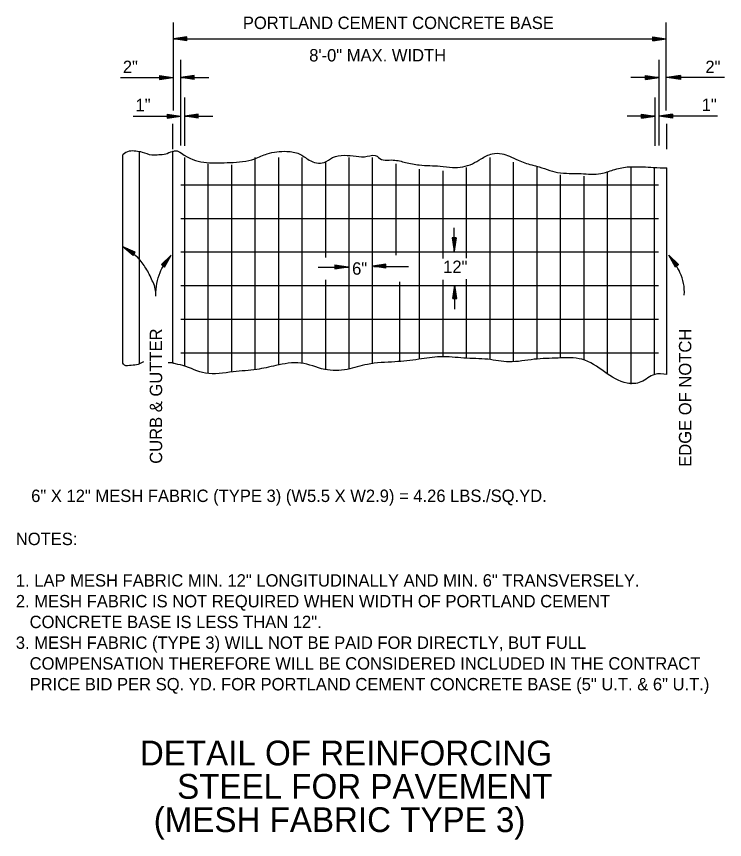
# Model space of a CAD drawing. Extents: x 635488 to 635865, y 290537 to 290973.
# Drawn here: x 635642.05 to 635676.35, y 290881.35 to 290921.21 of the extents above; entities that cross this region are included whole.
import ezdxf

# ---------------------------------------------------------------- set-up
doc = ezdxf.new("R2010")
doc.units = 0
doc.layers.add('E_Existing ROW', color=7, linetype='Continuous')

msp = doc.modelspace()

# ---------------------------------------------------------------- linework, layer by layer
at = {"layer": 'E_Existing ROW'}
for p, q in [((635649.657, 290916.655), (635649.657, 290920.918)), ((635673.528, 290916.655), (635673.528, 290920.918)), ((635650.307, 290920.228), (635649.657, 290920.13)), ((635649.657, 290920.13), (635673.528, 290920.13)), ((635650.307, 290920.033), (635649.657, 290920.13)), ((635650.307, 290920.211), (635649.765, 290920.13)), ((635650.307, 290920.049), (635649.765, 290920.13)), ((635650.307, 290920.195), (635649.877, 290920.13)), ((635650.307, 290920.066), (635649.877, 290920.13)), ((635650.307, 290920.178), (635649.985, 290920.13)), ((635650.307, 290920.082), (635649.985, 290920.13)), ((635650.307, 290920.162), (635650.096, 290920.13)), ((635650.307, 290920.099), (635650.096, 290920.13)), ((635650.307, 290920.145), (635650.204, 290920.13)), ((635650.307, 290920.115), (635650.204, 290920.13)), ((635650.307, 290920.033), (635650.307, 290920.228)), ((635672.879, 290920.228), (635673.529, 290920.13)), ((635672.879, 290920.033), (635672.879, 290920.228)), ((635672.879, 290920.211), (635673.42, 290920.13)), ((635672.879, 290920.195), (635673.309, 290920.13)), ((635672.879, 290920.178), (635673.201, 290920.13)), ((635672.879, 290920.162), (635673.09, 290920.13)), ((635672.879, 290920.145), (635672.981, 290920.13)), ((635672.879, 290920.033), (635673.529, 290920.13)), ((635672.879, 290920.099), (635673.09, 290920.13)), ((635672.879, 290920.066), (635673.309, 290920.13)), ((635672.879, 290920.049), (635673.42, 290920.13)), ((635672.879, 290920.082), (635673.201, 290920.13)), ((635672.879, 290920.115), (635672.981, 290920.13)), ((635650.005, 290914.965), (635650.005, 290919.111)), ((635673.18, 290914.965), (635673.18, 290919.111)), ((635648.969, 290918.353), (635649.62, 290918.256)), ((635648.969, 290918.353), (635648.969, 290918.158)), ((635648.969, 290918.337), (635649.511, 290918.256)), ((635648.969, 290918.32), (635649.399, 290918.256)), ((635648.969, 290918.304), (635649.291, 290918.256)), ((635650.656, 290918.353), (635650.005, 290918.256)), ((635650.656, 290918.337), (635650.114, 290918.256)), ((635650.656, 290918.32), (635650.226, 290918.256)), ((635650.656, 290918.304), (635650.334, 290918.256)), ((635650.656, 290918.158), (635650.656, 290918.353)), ((635672.529, 290918.353), (635673.18, 290918.256)), ((635672.529, 290918.158), (635672.529, 290918.353)), ((635672.529, 290918.337), (635673.071, 290918.256)), ((635672.529, 290918.32), (635672.959, 290918.256)), ((635672.529, 290918.304), (635672.851, 290918.256)), ((635674.216, 290918.353), (635673.565, 290918.256)), ((635674.216, 290918.337), (635673.674, 290918.256)), ((635674.216, 290918.32), (635673.786, 290918.256)), ((635674.216, 290918.304), (635673.894, 290918.256)), ((635674.216, 290918.353), (635674.216, 290918.158)), ((635647.09, 290918.256), (635649.657, 290918.256)), ((635648.969, 290918.287), (635649.181, 290918.256)), ((635648.969, 290918.27), (635649.072, 290918.256)), ((635648.969, 290918.158), (635649.62, 290918.256)), ((635648.969, 290918.224), (635649.181, 290918.256)), ((635648.969, 290918.191), (635649.399, 290918.256)), ((635648.969, 290918.174), (635649.511, 290918.256)), ((635648.969, 290918.207), (635649.291, 290918.256)), ((635648.969, 290918.241), (635649.072, 290918.256)), ((635650.656, 290918.158), (635650.005, 290918.256)), ((635650.005, 290918.256), (635651.363, 290918.256)), ((635650.656, 290918.174), (635650.114, 290918.256)), ((635650.656, 290918.191), (635650.226, 290918.256)), ((635650.656, 290918.207), (635650.334, 290918.256)), ((635650.656, 290918.287), (635650.444, 290918.256)), ((635650.656, 290918.224), (635650.444, 290918.256)), ((635650.656, 290918.27), (635650.553, 290918.256)), ((635650.656, 290918.241), (635650.553, 290918.256)), ((635673.18, 290918.256), (635671.822, 290918.256)), ((635672.529, 290918.287), (635672.741, 290918.256)), ((635672.529, 290918.27), (635672.632, 290918.256)), ((635672.529, 290918.158), (635673.18, 290918.256)), ((635672.529, 290918.224), (635672.741, 290918.256)), ((635672.529, 290918.191), (635672.959, 290918.256)), ((635672.529, 290918.174), (635673.071, 290918.256)), ((635672.529, 290918.207), (635672.851, 290918.256)), ((635672.529, 290918.241), (635672.632, 290918.256)), ((635676.355, 290918.256), (635673.528, 290918.256)), ((635674.216, 290918.158), (635673.565, 290918.256)), ((635674.216, 290918.174), (635673.674, 290918.256)), ((635674.216, 290918.191), (635673.786, 290918.256)), ((635674.216, 290918.207), (635673.894, 290918.256)), ((635674.216, 290918.287), (635674.004, 290918.256)), ((635674.216, 290918.224), (635674.004, 290918.256)), ((635674.216, 290918.27), (635674.113, 290918.256)), ((635674.216, 290918.241), (635674.113, 290918.256)), ((635650.199, 290914.942), (635650.199, 290917.287)), ((635672.986, 290914.942), (635672.986, 290917.287)), ((635647.697, 290916.372), (635650.005, 290916.372)), ((635649.355, 290916.47), (635650.005, 290916.372)), ((635649.355, 290916.47), (635649.355, 290916.275)), ((635649.355, 290916.453), (635649.897, 290916.372)), ((635649.355, 290916.436), (635649.785, 290916.372)), ((635649.355, 290916.42), (635649.677, 290916.372)), ((635649.355, 290916.403), (635649.566, 290916.372)), ((635649.355, 290916.387), (635649.458, 290916.372)), ((635649.355, 290916.275), (635650.005, 290916.372)), ((635649.355, 290916.34), (635649.566, 290916.372)), ((635649.355, 290916.308), (635649.785, 290916.372)), ((635649.355, 290916.291), (635649.897, 290916.372)), ((635649.355, 290916.324), (635649.677, 290916.372)), ((635649.355, 290916.357), (635649.458, 290916.372)), ((635649.504, 290916.372), (635650.005, 290916.372)), ((635650.849, 290916.47), (635650.199, 290916.372)), ((635650.849, 290916.275), (635650.199, 290916.372)), ((635650.199, 290916.372), (635651.557, 290916.372)), ((635650.849, 290916.453), (635650.307, 290916.372)), ((635650.849, 290916.291), (635650.307, 290916.372)), ((635650.849, 290916.436), (635650.419, 290916.372)), ((635650.849, 290916.308), (635650.419, 290916.372)), ((635650.849, 290916.42), (635650.527, 290916.372)), ((635650.849, 290916.324), (635650.527, 290916.372)), ((635650.849, 290916.404), (635650.638, 290916.372)), ((635650.849, 290916.341), (635650.638, 290916.372)), ((635650.849, 290916.387), (635650.746, 290916.372)), ((635650.849, 290916.357), (635650.746, 290916.372)), ((635650.849, 290916.275), (635650.849, 290916.47)), ((635672.986, 290916.372), (635671.629, 290916.372)), ((635672.336, 290916.47), (635672.986, 290916.372)), ((635672.336, 290916.275), (635672.336, 290916.47)), ((635672.336, 290916.453), (635672.878, 290916.372)), ((635672.336, 290916.436), (635672.766, 290916.372)), ((635672.336, 290916.42), (635672.658, 290916.372)), ((635672.336, 290916.404), (635672.547, 290916.372)), ((635672.336, 290916.387), (635672.439, 290916.372)), ((635672.336, 290916.275), (635672.986, 290916.372)), ((635672.336, 290916.341), (635672.547, 290916.372)), ((635672.336, 290916.308), (635672.766, 290916.372)), ((635672.336, 290916.291), (635672.878, 290916.372)), ((635672.336, 290916.324), (635672.658, 290916.372)), ((635672.336, 290916.357), (635672.439, 290916.372)), ((635673.83, 290916.47), (635673.18, 290916.372)), ((635673.83, 290916.275), (635673.18, 290916.372)), ((635676.006, 290916.372), (635673.18, 290916.372)), ((635673.83, 290916.453), (635673.288, 290916.372)), ((635673.83, 290916.291), (635673.288, 290916.372)), ((635673.83, 290916.436), (635673.4, 290916.372)), ((635673.83, 290916.308), (635673.4, 290916.372)), ((635673.83, 290916.42), (635673.508, 290916.372)), ((635673.83, 290916.324), (635673.508, 290916.372)), ((635673.83, 290916.403), (635673.619, 290916.372)), ((635673.83, 290916.34), (635673.619, 290916.372)), ((635673.83, 290916.387), (635673.727, 290916.372)), ((635673.83, 290916.357), (635673.727, 290916.372)), ((635673.83, 290916.47), (635673.83, 290916.275)), ((635649.627, 290914.775), (635649.627, 290916.012)), ((635673.558, 290914.775), (635673.558, 290916.012)), ((635647.197, 290904.415), (635647.197, 290914.524)), ((635648.007, 290904.415), (635648.007, 290914.667)), ((635649.627, 290904.415), (635649.627, 290914.667)), ((635650.199, 290904.276), (635650.199, 290914.384)), ((635653.613, 290904.108), (635653.613, 290914.384)), ((635654.751, 290904.326), (635654.751, 290914.384)), ((635655.889, 290904.421), (635655.889, 290914.384)), ((635658.166, 290904.136), (635658.166, 290914.384)), ((635659.304, 290904.387), (635659.304, 290914.384)), ((635664.995, 290904.597), (635664.995, 290914.384)), ((635651.337, 290903.926), (635651.337, 290914.076)), ((635652.475, 290903.991), (635652.475, 290914.016)), ((635657.028, 290909.54), (635657.028, 290914.152)), ((635660.442, 290909.649), (635660.442, 290914.076)), ((635666.133, 290908.177), (635666.133, 290914.152)), ((635667.271, 290908.177), (635667.271, 290913.938)), ((635661.58, 290904.61), (635661.58, 290913.811)), ((635662.718, 290909.48), (635662.718, 290913.725)), ((635663.856, 290909.509), (635663.856, 290913.897)), ((635668.409, 290904.672), (635668.409, 290913.537)), ((635670.685, 290903.921), (635670.685, 290913.657)), ((635671.823, 290903.41), (635671.823, 290913.898)), ((635672.961, 290903.873), (635672.961, 290913.871)), ((635673.558, 290903.873), (635673.558, 290913.871)), ((635669.547, 290904.565), (635669.547, 290913.477)), ((635650.005, 290913.055), (635672.902, 290913.055)), ((635672.902, 290913.055), (635673.151, 290913.055)), ((635650.005, 290911.429), (635672.602, 290911.429)), ((635672.602, 290911.429), (635673.151, 290911.429)), ((635663.255, 290909.84), (635663.255, 290910.966)), ((635663.157, 290910.49), (635663.255, 290909.84)), ((635663.352, 290910.49), (635663.157, 290910.49)), ((635663.173, 290910.49), (635663.255, 290909.948)), ((635663.19, 290910.49), (635663.255, 290910.06)), ((635663.207, 290910.49), (635663.255, 290910.168)), ((635663.223, 290910.49), (635663.255, 290910.279)), ((635663.24, 290910.49), (635663.255, 290910.387)), ((635663.352, 290910.49), (635663.255, 290909.84)), ((635663.286, 290910.49), (635663.255, 290910.279)), ((635663.319, 290910.49), (635663.255, 290910.06)), ((635663.336, 290910.49), (635663.255, 290909.948)), ((635663.303, 290910.49), (635663.255, 290910.168)), ((635663.27, 290910.49), (635663.255, 290910.387)), ((635647.702, 290909.632), (635647.196, 290910.053)), ((635647.803, 290909.799), (635647.196, 290910.053)), ((635647.711, 290909.646), (635647.289, 290909.996)), ((635647.795, 290909.785), (635647.289, 290909.996)), ((635647.786, 290909.771), (635647.385, 290909.939)), ((635647.719, 290909.66), (635647.385, 290909.939)), ((635647.728, 290909.674), (635647.477, 290909.882)), ((635647.778, 290909.757), (635647.477, 290909.882)), ((635647.769, 290909.743), (635647.572, 290909.825)), ((635647.736, 290909.689), (635647.572, 290909.825)), ((635647.761, 290909.728), (635647.665, 290909.769)), ((635647.745, 290909.703), (635647.665, 290909.769)), ((635647.702, 290909.632), (635647.803, 290909.799)), ((635649.071, 290909.196), (635649.55, 290909.646)), ((635649.084, 290909.185), (635649.483, 290909.561)), ((635649.211, 290909.085), (635649.483, 290909.561)), ((635649.224, 290909.075), (635649.55, 290909.646)), ((635650.005, 290909.803), (635660.388, 290909.803)), ((635660.388, 290909.803), (635672.645, 290909.803)), ((635672.645, 290909.803), (635673.151, 290909.803)), ((635674.129, 290909.196), (635673.65, 290909.646)), ((635673.975, 290909.075), (635673.65, 290909.646)), ((635674.116, 290909.185), (635673.717, 290909.561)), ((635673.988, 290909.085), (635673.717, 290909.561)), ((635649.071, 290909.196), (635649.224, 290909.075)), ((635649.097, 290909.175), (635649.414, 290909.473)), ((635649.109, 290909.165), (635649.347, 290909.388)), ((635649.123, 290909.155), (635649.278, 290909.301)), ((635649.136, 290909.144), (635649.211, 290909.216)), ((635649.159, 290909.126), (635649.211, 290909.216)), ((635649.173, 290909.116), (635649.278, 290909.301)), ((635649.186, 290909.105), (635649.347, 290909.388)), ((635649.198, 290909.095), (635649.414, 290909.473)), ((635657.475, 290909.189), (635658.125, 290909.092)), ((635657.475, 290909.189), (635657.475, 290908.994)), ((635657.475, 290909.173), (635658.017, 290909.092)), ((635657.475, 290909.156), (635657.905, 290909.092)), ((635657.475, 290909.14), (635657.797, 290909.092)), ((635659.95, 290909.221), (635659.3, 290909.123)), ((635659.95, 290909.204), (635659.409, 290909.123)), ((635659.95, 290909.188), (635659.52, 290909.123)), ((635659.95, 290909.171), (635659.628, 290909.123)), ((635659.95, 290909.155), (635659.739, 290909.123)), ((635659.95, 290909.138), (635659.848, 290909.123)), ((635659.95, 290909.026), (635659.95, 290909.221)), ((635674.001, 290909.095), (635673.786, 290909.473)), ((635674.103, 290909.175), (635673.786, 290909.473)), ((635674.09, 290909.165), (635673.853, 290909.388)), ((635674.014, 290909.105), (635673.853, 290909.388)), ((635674.027, 290909.116), (635673.921, 290909.301)), ((635674.077, 290909.155), (635673.921, 290909.301)), ((635674.129, 290909.196), (635673.975, 290909.075)), ((635674.04, 290909.126), (635673.988, 290909.216)), ((635674.064, 290909.144), (635673.988, 290909.216)), ((635656.666, 290909.062), (635658.125, 290909.062)), ((635657.475, 290909.123), (635657.686, 290909.092)), ((635657.475, 290909.107), (635657.578, 290909.092)), ((635657.475, 290908.994), (635658.125, 290909.092)), ((635657.475, 290909.06), (635657.686, 290909.092)), ((635657.475, 290909.028), (635657.905, 290909.092)), ((635657.475, 290909.011), (635658.017, 290909.092)), ((635657.475, 290909.044), (635657.797, 290909.092)), ((635657.475, 290909.077), (635657.578, 290909.092)), ((635659.95, 290909.026), (635659.3, 290909.123)), ((635659.36, 290909.093), (635661.044, 290909.093)), ((635659.95, 290909.042), (635659.409, 290909.123)), ((635659.95, 290909.059), (635659.52, 290909.123)), ((635659.95, 290909.075), (635659.628, 290909.123)), ((635659.95, 290909.092), (635659.739, 290909.123)), ((635659.95, 290909.108), (635659.848, 290909.123)), ((635657.028, 290904.114), (635657.028, 290908.462)), ((635660.619, 290904.508), (635660.619, 290908.365)), ((635662.718, 290904.721), (635662.718, 290908.462)), ((635663.856, 290908.177), (635663.856, 290908.492)), ((635663.856, 290904.659), (635663.856, 290908.455)), ((635666.133, 290904.493), (635666.133, 290908.455)), ((635667.271, 290904.615), (635667.271, 290908.507)), ((635650.005, 290908.177), (635672.56, 290908.177)), ((635663.188, 290907.547), (635663.285, 290908.197)), ((635663.204, 290907.547), (635663.285, 290908.088)), ((635663.221, 290907.547), (635663.285, 290907.977)), ((635663.383, 290907.547), (635663.285, 290908.197)), ((635663.285, 290907.041), (635663.285, 290908.167)), ((635663.367, 290907.547), (635663.285, 290908.088)), ((635663.35, 290907.547), (635663.285, 290907.977)), ((635672.56, 290908.177), (635673.151, 290908.177)), ((635663.188, 290907.547), (635663.383, 290907.547)), ((635663.237, 290907.547), (635663.285, 290907.869)), ((635663.254, 290907.547), (635663.285, 290907.758)), ((635663.27, 290907.547), (635663.285, 290907.649)), ((635663.333, 290907.547), (635663.285, 290907.869)), ((635663.317, 290907.547), (635663.285, 290907.758)), ((635663.3, 290907.547), (635663.285, 290907.649)), ((635650.005, 290906.551), (635672.645, 290906.551)), ((635672.645, 290906.551), (635673.151, 290906.551)), ((635650.005, 290904.925), (635672.774, 290904.925)), ((635672.774, 290904.925), (635673.151, 290904.925))]:
    msp.add_line(p, q, dxfattribs=at)
for points in [[(635649.627, 290914.667), (635649.639, 290914.675), (635650.179, 290914.496), (635651.257, 290914.136), (635652.395, 290914.136), (635653.593, 290914.316), (635654.192, 290914.556), (635655.151, 290914.675), (635655.75, 290914.556), (635656.229, 290914.256), (635656.948, 290914.136), (635657.367, 290914.376), (635658.505, 290914.436), (635659.044, 290914.436), (635659.523, 290914.436), (635659.583, 290914.376), (635660.302, 290914.256), (635660.901, 290914.136), (635661.56, 290914.016), (635662.578, 290913.957), (635663.177, 290913.897), (635664.135, 290914.076), (635664.555, 290914.316), (635665.094, 290914.556), (635665.573, 290914.556), (635665.932, 290914.436), (635666.352, 290914.256), (635667.011, 290914.016), (635667.25, 290913.957), (635668.268, 290913.657), (635669.407, 290913.597), (635670.365, 290913.597), (635670.964, 290913.777), (635671.634, 290913.926)], [(635649.627, 290914.667), (635649.588, 290914.659), (635649.277, 290914.535), (635648.945, 290914.504), (635648.613, 290914.493), (635648.157, 290914.628), (635647.835, 290914.68), (635647.503, 290914.68), (635647.212, 290914.524)], [(635671.634, 290913.926), (635672.389, 290913.926), (635672.904, 290913.896), (635673.558, 290913.871)], [(635648.796, 290907.667), (635648.795, 290907.77), (635648.753, 290908.102), (635648.629, 290908.413), (635648.483, 290908.725), (635648.317, 290909.015), (635648.131, 290909.285), (635647.923, 290909.534), (635647.674, 290909.741), (635647.425, 290909.949), (635647.196, 290910.053)], [(635648.796, 290907.667), (635648.797, 290907.723), (635649.005, 290908.813), (635649.438, 290909.543)], [(635674.402, 290907.712), (635674.403, 290907.723), (635674.195, 290908.813), (635673.758, 290909.547)], [(635648.195, 290904.491), (635647.939, 290904.356), (635647.607, 290904.315), (635647.275, 290904.325), (635647.197, 290904.415)], [(635649.627, 290904.415), (635649.651, 290904.419), (635649.396, 290904.431)], [(635673.558, 290903.873), (635672.972, 290903.876), (635672.303, 290903.511), (635671.634, 290903.45), (635670.54, 290903.998), (635669.445, 290904.606), (635668.29, 290904.666), (635667.135, 290904.606), (635665.918, 290904.484), (635664.885, 290904.606), (635663.729, 290904.666), (635662.574, 290904.727), (635661.54, 290904.606), (635660.385, 290904.484), (635659.047, 290904.362), (635658.074, 290904.119), (635656.98, 290904.119), (635655.825, 290904.423), (635654.609, 290904.301), (635653.696, 290904.119), (635652.541, 290903.998), (635651.203, 290903.936), (635650.109, 290904.301), (635649.627, 290904.415)]]:
    msp.add_spline(points, degree=3, dxfattribs=at)

# ---------------------------------------------------------------- texts
for s, height, p in [('PORTLAND CEMENT CONCRETE BASE', 0.6, (635653.016, 290920.599)), ('8\'-0" MAX. WIDTH', 0.6, (635656.23, 290919.03)), ('2"', 0.6, (635647.2, 290918.467)), ('2"', 0.6, (635675.426, 290918.467)), ('1"', 0.6, (635647.815, 290916.62)), ('1"', 0.6, (635675.247, 290916.631)), ('6"', 0.6, (635658.31, 290908.704)), ('12"', 0.6, (635662.72, 290908.786)), ('6" X 12" MESH FABRIC (TYPE 3) (W5.5 X W2.9) = 4.26 LBS./SQ.YD.', 0.6, (635642.759, 290897.697)), ('NOTES:', 0.6, (635642.015, 290895.611)), ('1. LAP MESH FABRIC MIN. 12" LONGITUDINALLY AND MIN. 6" TRANSVERSELY.', 0.6, (635642.015, 290893.601)), ('2. MESH FABRIC IS NOT REQUIRED WHEN WIDTH OF PORTLAND CEMENT', 0.6, (635642.015, 290892.596)), ('   CONCRETE BASE IS LESS THAN 12".', 0.6, (635642.015, 290891.591)), ('3. MESH FABRIC (TYPE 3) WILL NOT BE PAID FOR DIRECTLY, BUT FULL', 0.6, (635642.015, 290890.586)), ('   COMPENSATION THEREFORE WILL BE CONSIDERED INCLUDED IN THE CONTRACT', 0.6, (635642.015, 290889.581)), ('   PRICE BID PER SQ. YD. FOR PORTLAND CEMENT CONCRETE BASE (5" U.T. & 6" U.T.)', 0.6, (635642.015, 290888.576)), ('DETAIL OF REINFORCING', 1.2, (635648.025, 290884.943)), ('STEEL FOR PAVEMENT', 1.2, (635649.831, 290883.329)), ('(MESH FABRIC TYPE 3)', 1.2, (635648.695, 290881.715))]:
    msp.add_text(s, height=height, dxfattribs=at).set_placement(p)
for s, p in [('CURB & GUTTER', (635649.105, 290899.548)), ('EDGE OF NOTCH', (635674.745, 290899.402))]:
    msp.add_text(s, height=0.6, rotation=90, dxfattribs=at).set_placement(p)

doc.saveas('drawing.dxf')
